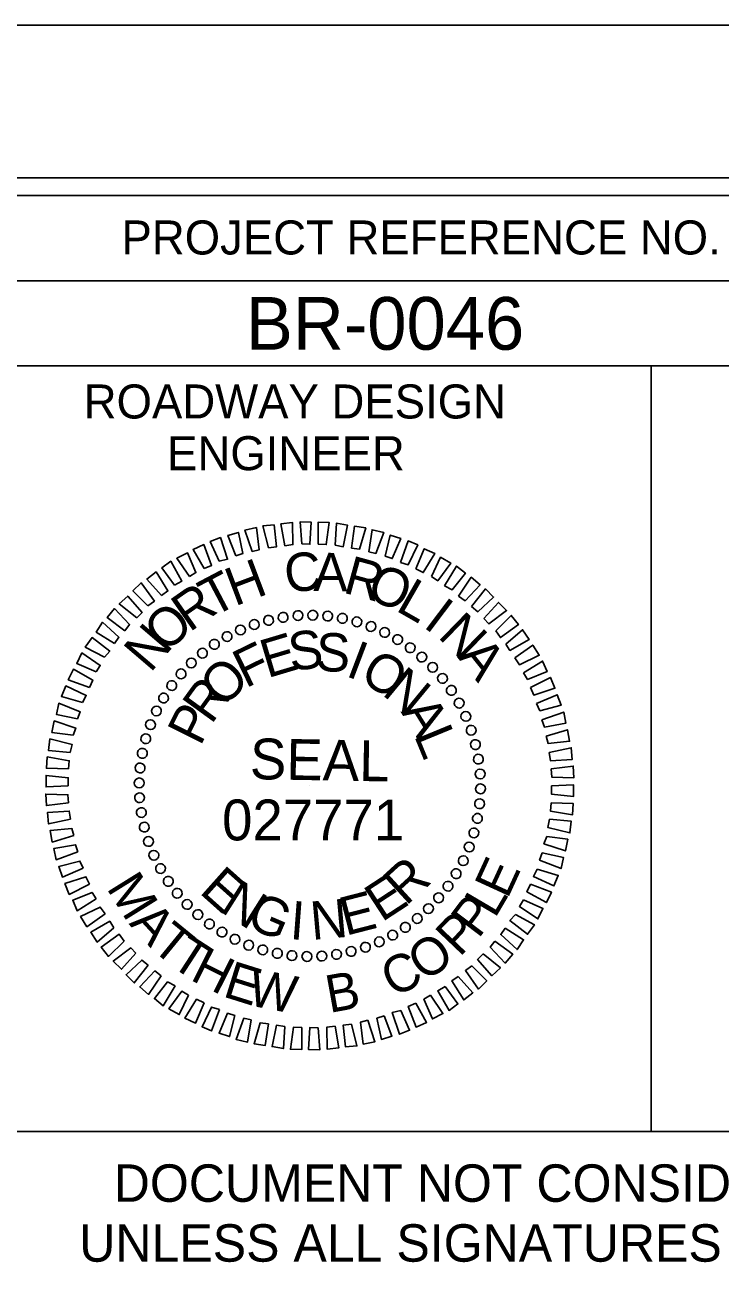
# Model space of a CAD drawing. Extents: x 1019474 to 1021158, y 503201 to 504732.
# Drawn here: x 1020949.2 to 1021051.4, y 504115.2 to 504300.7 of the extents above; entities that cross this region are included whole.
import ezdxf

# ---------------------------------------------------------------- set-up
doc = ezdxf.new("R2010")
doc.units = 0
for name, color, linetype in [('Sheet Cutting Line CELL', 7, 'Continuous'), ('Sheet Data Field CELL', 7, 'Continuous'), ('Sheet Plot Border Inside CELL', 7, 'Continuous'), ('Sheet Plot Border Outside CELL', 7, 'Continuous'), ('Sheet Professional Seal CELL', 7, 'Continuous'), ('Sheet Profile CELL', 7, 'Continuous'), ('Sheet Sticker Exception Certification CELL', 7, 'Continuous')]:
    doc.layers.add(name, color=color, linetype=linetype)

msp = doc.modelspace()

# ---------------------------------------------------------------- linework, layer by layer
at = {"layer": 'Sheet Cutting Line CELL'}
msp.add_line((1021158.22, 504300.7), (1019474.22, 504300.7), dxfattribs=at)
at = {"layer": 'Sheet Plot Border Inside CELL'}
msp.add_lwpolyline([(1019487.22, 503223.15), (1021153.72, 503223.15), (1021153.72, 504278.25), (1019487.22, 504278.25)], close=True, dxfattribs=at)
at = {"layer": 'Sheet Plot Border Outside CELL'}
msp.add_lwpolyline([(1019474.22, 503200.7), (1021158.22, 503200.7), (1021158.22, 504300.7), (1019474.22, 504300.7)], close=True, dxfattribs=at)
at = {"layer": 'Sheet Professional Seal CELL'}
for p, q in [((1020982.86, 504212.67), (1020982.86, 504212.67)), ((1020984.96, 504213.27), (1020984.96, 504213.27)), ((1020987.16, 504213.67), (1020987.16, 504213.67)), ((1020989.31, 504213.97), (1020989.31, 504213.97)), ((1020991.51, 504214.02), (1020991.51, 504214.02)), ((1020993.71, 504213.87), (1020993.71, 504213.87)), ((1020995.86, 504213.52), (1020995.86, 504213.52)), ((1020997.96, 504213.07), (1020997.96, 504213.07)), ((1020978.91, 504210.87), (1020978.91, 504210.87)), ((1020980.86, 504211.87), (1020980.86, 504211.87)), ((1021000.06, 504212.37), (1021000.06, 504212.37)), ((1021002.06, 504211.47), (1021002.06, 504211.47)), ((1020977.01, 504209.72), (1020977.01, 504209.72)), ((1021004.01, 504210.47), (1021004.01, 504210.47)), ((1021005.81, 504209.22), (1021005.81, 504209.22)), ((1020973.61, 504206.97), (1020973.61, 504206.97)), ((1020975.26, 504208.47), (1020975.26, 504208.47)), ((1021007.56, 504207.87), (1021007.56, 504207.87)), ((1020972.11, 504205.42), (1020972.11, 504205.42)), ((1021009.11, 504206.37), (1021009.11, 504206.37)), ((1020970.76, 504203.67), (1020970.76, 504203.67)), ((1021010.61, 504204.72), (1021010.61, 504204.72)), ((1020969.51, 504201.87), (1020969.51, 504201.87)), ((1021011.86, 504202.97), (1021011.86, 504202.97)), ((1020968.51, 504199.92), (1020968.51, 504199.92)), ((1021013.01, 504201.07), (1021013.01, 504201.07)), ((1020967.61, 504197.92), (1020967.61, 504197.92)), ((1021014.01, 504199.12), (1021014.01, 504199.12)), ((1020966.91, 504195.82), (1020966.91, 504195.82)), ((1021014.81, 504197.12), (1021014.81, 504197.12)), ((1021015.41, 504195.02), (1021015.41, 504195.02)), ((1020966.46, 504193.72), (1020966.46, 504193.72)), ((1021015.81, 504192.82), (1021015.81, 504192.82)), ((1020966.11, 504191.57), (1020966.11, 504191.57)), ((1021016.11, 504190.67), (1021016.11, 504190.67)), ((1020965.96, 504189.37), (1020965.96, 504189.37)), ((1020991.06, 504188.92), (1020991.06, 504188.92)), ((1021016.16, 504188.47), (1021016.16, 504188.47)), ((1020966.01, 504187.17), (1020966.01, 504187.17)), ((1020966.31, 504185.02), (1020966.31, 504185.02)), ((1021016.01, 504186.27), (1021016.01, 504186.27)), ((1020966.71, 504182.82), (1020966.71, 504182.82)), ((1021015.66, 504184.12), (1021015.66, 504184.12)), ((1021015.21, 504182.02), (1021015.21, 504182.02)), ((1020967.31, 504180.72), (1020967.31, 504180.72)), ((1021014.51, 504179.92), (1021014.51, 504179.92)), ((1020968.11, 504178.72), (1020968.11, 504178.72)), ((1021013.61, 504177.92), (1021013.61, 504177.92)), ((1020969.11, 504176.77), (1020969.11, 504176.77)), ((1021012.61, 504175.97), (1021012.61, 504175.97)), ((1020970.26, 504174.87), (1020970.26, 504174.87)), ((1021011.36, 504174.17), (1021011.36, 504174.17)), ((1020971.51, 504173.12), (1020971.51, 504173.12)), ((1021010.01, 504172.42), (1021010.01, 504172.42)), ((1020973.01, 504171.47), (1020973.01, 504171.47)), ((1020974.56, 504169.97), (1020974.56, 504169.97)), ((1021008.51, 504170.87), (1021008.51, 504170.87)), ((1020976.31, 504168.62), (1020976.31, 504168.62)), ((1021005.11, 504168.12), (1021005.11, 504168.12)), ((1021006.86, 504169.37), (1021006.86, 504169.37)), ((1020978.11, 504167.37), (1020978.11, 504167.37)), ((1020980.06, 504166.37), (1020980.06, 504166.37)), ((1021003.21, 504166.97), (1021003.21, 504166.97)), ((1020982.06, 504165.47), (1020982.06, 504165.47)), ((1020984.16, 504164.77), (1020984.16, 504164.77)), ((1020986.26, 504164.32), (1020986.26, 504164.32)), ((1020997.16, 504164.57), (1020997.16, 504164.57)), ((1020999.26, 504165.17), (1020999.26, 504165.17)), ((1021001.26, 504165.97), (1021001.26, 504165.97)), ((1020988.41, 504163.97), (1020988.41, 504163.97)), ((1020990.61, 504163.82), (1020990.61, 504163.82)), ((1020992.81, 504163.87), (1020992.81, 504163.87)), ((1020994.96, 504164.17), (1020994.96, 504164.17))]:
    msp.add_line(p, q, dxfattribs=at)
for points in [[(1020984.96, 504223.92), (1020984.16, 504227.12), (1020985.81, 504227.27), (1020986.16, 504224.07)], [(1020987.36, 504224.22), (1020986.81, 504227.42), (1020988.51, 504227.62), (1020988.56, 504224.37)], [(1020989.86, 504224.47), (1020989.61, 504227.72), (1020991.26, 504227.67), (1020991.06, 504224.42)], [(1020992.26, 504224.42), (1020992.26, 504227.67), (1020993.91, 504227.62), (1020993.46, 504224.37)], [(1020994.76, 504224.27), (1020994.96, 504227.52), (1020996.61, 504227.22), (1020995.96, 504224.07)], [(1020977.71, 504221.92), (1020976.41, 504224.82), (1020977.91, 504225.42), (1020978.96, 504222.22)], [(1020980.16, 504222.72), (1020979.01, 504225.72), (1020980.56, 504226.17), (1020981.21, 504223.07)], [(1020982.56, 504223.37), (1020981.51, 504226.52), (1020983.21, 504226.87), (1020983.61, 504223.62)], [(1020997.16, 504223.87), (1020997.61, 504227.07), (1020999.26, 504226.82), (1020998.36, 504223.72)], [(1020999.71, 504223.32), (1021000.21, 504226.57), (1021001.91, 504226.17), (1021000.76, 504223.07)], [(1021002.11, 504222.67), (1021002.86, 504225.77), (1021004.41, 504225.27), (1021003.16, 504222.32)], [(1020975.51, 504220.87), (1020973.91, 504223.67), (1020975.46, 504224.37), (1020976.61, 504221.32)], [(1021004.36, 504221.77), (1021005.51, 504224.92), (1021006.91, 504224.32), (1021005.51, 504221.42)], [(1021006.61, 504220.82), (1021007.86, 504223.77), (1021009.41, 504223.07), (1021007.71, 504220.27)], [(1020971.16, 504218.42), (1020969.31, 504220.97), (1020970.61, 504221.92), (1020972.26, 504219.02)], [(1020973.36, 504219.67), (1020971.51, 504222.37), (1020973.06, 504223.17), (1020974.31, 504220.27)], [(1021008.91, 504219.67), (1021010.26, 504222.52), (1021011.76, 504221.67), (1021009.86, 504219.07)], [(1020969.26, 504216.92), (1020967.11, 504219.32), (1020968.46, 504220.37), (1020970.21, 504217.57)], [(1021010.86, 504218.32), (1021012.61, 504221.22), (1021013.91, 504220.17), (1021011.96, 504217.72)], [(1020967.26, 504215.37), (1020965.06, 504217.57), (1020966.26, 504218.77), (1020968.21, 504216.07)], [(1021012.91, 504216.82), (1021014.76, 504219.57), (1021016.06, 504218.47), (1021013.86, 504216.12)], [(1020965.61, 504213.62), (1020963.06, 504215.67), (1020964.31, 504216.82), (1020966.41, 504214.42)], [(1021014.81, 504215.27), (1021016.86, 504217.87), (1021018.06, 504216.67), (1021015.76, 504214.52)], [(1020963.86, 504211.72), (1020961.26, 504213.67), (1020962.36, 504214.97), (1020964.56, 504212.62)], [(1021016.61, 504213.52), (1021018.76, 504215.87), (1021019.96, 504214.67), (1021017.36, 504212.72)], [(1020962.36, 504209.82), (1020959.66, 504211.52), (1020960.61, 504212.97), (1020963.01, 504210.77)], [(1021018.36, 504211.72), (1021020.66, 504213.97), (1021021.71, 504212.62), (1021019.06, 504210.72)], [(1020960.86, 504207.82), (1020958.06, 504209.32), (1020959.06, 504210.72), (1020961.66, 504208.72)], [(1021019.86, 504209.77), (1021022.31, 504211.87), (1021023.26, 504210.42), (1021020.46, 504208.82)], [(1021021.16, 504207.72), (1021023.81, 504209.62), (1021024.76, 504208.12), (1021021.86, 504206.72)], [(1020959.66, 504205.67), (1020956.81, 504206.92), (1020957.56, 504208.47), (1020960.26, 504206.62)], [(1021022.46, 504205.52), (1021025.26, 504207.27), (1021025.91, 504205.72), (1021023.06, 504204.57)], [(1020958.66, 504203.37), (1020955.56, 504204.52), (1020956.31, 504206.07), (1020959.16, 504204.47)], [(1020957.66, 504201.17), (1020954.56, 504202.07), (1020955.21, 504203.62), (1020958.21, 504202.22)], [(1021023.46, 504203.37), (1021026.41, 504204.87), (1021027.06, 504203.27), (1021023.96, 504202.27)], [(1021024.36, 504201.02), (1021027.41, 504202.32), (1021027.96, 504200.77), (1021024.86, 504199.97)], [(1020956.91, 504198.77), (1020953.81, 504199.42), (1020954.16, 504201.07), (1020957.31, 504199.82)], [(1021025.16, 504198.62), (1021028.36, 504199.77), (1021028.66, 504198.12), (1021025.51, 504197.57)], [(1020956.26, 504196.37), (1020953.16, 504196.77), (1020953.51, 504198.47), (1020956.66, 504197.42)], [(1020955.86, 504193.82), (1020952.66, 504194.12), (1020952.86, 504195.82), (1020956.11, 504195.02)], [(1021025.76, 504196.22), (1021028.91, 504197.17), (1021029.21, 504195.47), (1021026.06, 504195.17)], [(1021026.21, 504193.82), (1021029.46, 504194.52), (1021029.61, 504192.82), (1021026.41, 504192.62)], [(1020955.61, 504191.42), (1020952.36, 504191.52), (1020952.46, 504193.17), (1020955.71, 504192.62)], [(1020955.56, 504188.92), (1020952.31, 504188.77), (1020952.31, 504190.47), (1020955.56, 504190.12)], [(1021026.51, 504191.42), (1021029.76, 504191.82), (1021029.86, 504190.12), (1021026.61, 504190.22)], [(1021026.56, 504188.92), (1021029.81, 504189.07), (1021029.81, 504187.37), (1021026.56, 504187.72)], [(1020955.61, 504186.42), (1020952.36, 504186.02), (1020952.26, 504187.72), (1020955.51, 504187.62)], [(1020955.91, 504184.02), (1020952.66, 504183.32), (1020952.51, 504185.02), (1020955.71, 504185.22)], [(1021026.51, 504186.42), (1021029.76, 504186.32), (1021029.66, 504184.67), (1021026.41, 504185.22)], [(1021026.26, 504184.02), (1021029.46, 504183.72), (1021029.26, 504182.02), (1021026.01, 504182.82)], [(1020956.36, 504181.62), (1020953.21, 504180.67), (1020952.91, 504182.37), (1020956.06, 504182.67)], [(1021025.86, 504181.47), (1021028.96, 504181.07), (1021028.61, 504179.37), (1021025.46, 504180.42)], [(1020956.96, 504179.22), (1020953.76, 504178.07), (1020953.46, 504179.72), (1020956.61, 504180.27)], [(1021025.21, 504179.07), (1021028.31, 504178.42), (1021027.96, 504176.77), (1021024.81, 504178.02)], [(1020957.76, 504176.82), (1020954.71, 504175.52), (1020954.16, 504177.07), (1020957.26, 504177.87)], [(1020958.66, 504174.47), (1020955.71, 504172.97), (1020955.06, 504174.57), (1020958.16, 504175.57)], [(1021024.46, 504176.67), (1021027.56, 504175.77), (1021026.91, 504174.22), (1021023.91, 504175.62)], [(1021023.46, 504174.47), (1021026.56, 504173.32), (1021025.81, 504171.77), (1021022.96, 504173.37)], [(1020959.66, 504172.32), (1020956.86, 504170.57), (1020956.21, 504172.12), (1020959.06, 504173.27)], [(1021022.46, 504172.17), (1021025.31, 504170.92), (1021024.56, 504169.37), (1021021.86, 504171.22)], [(1020960.96, 504170.12), (1020958.31, 504168.22), (1020957.36, 504169.72), (1020960.26, 504171.12)], [(1021021.26, 504170.02), (1021024.06, 504168.52), (1021023.06, 504167.12), (1021020.46, 504169.12)], [(1020962.26, 504168.07), (1020959.81, 504165.97), (1020958.86, 504167.42), (1020961.66, 504169.02)], [(1021019.76, 504168.02), (1021022.46, 504166.32), (1021021.51, 504164.87), (1021019.11, 504167.07)], [(1020963.76, 504166.12), (1020961.46, 504163.87), (1020960.41, 504165.22), (1020963.06, 504167.12)], [(1021018.26, 504166.12), (1021020.86, 504164.17), (1021019.76, 504162.87), (1021017.56, 504165.22)], [(1020965.51, 504164.32), (1020963.36, 504161.97), (1020962.16, 504163.17), (1020964.76, 504165.12)], [(1021016.51, 504164.22), (1021019.06, 504162.17), (1021017.81, 504161.02), (1021015.71, 504163.42)], [(1020967.31, 504162.57), (1020965.26, 504159.97), (1020964.06, 504161.17), (1020966.36, 504163.32)], [(1021014.86, 504162.47), (1021017.06, 504160.27), (1021015.86, 504159.07), (1021013.91, 504161.77)], [(1020969.21, 504161.02), (1020967.36, 504158.27), (1020966.06, 504159.37), (1020968.26, 504161.72)], [(1021012.86, 504160.92), (1021015.01, 504158.52), (1021013.66, 504157.47), (1021011.91, 504160.27)], [(1020971.26, 504159.52), (1020969.51, 504156.62), (1020968.21, 504157.67), (1020970.16, 504160.12)], [(1020973.21, 504158.17), (1020971.86, 504155.32), (1020970.36, 504156.17), (1020972.26, 504158.77)], [(1021010.96, 504159.42), (1021012.81, 504156.87), (1021011.51, 504155.92), (1021009.86, 504158.82)], [(1020975.51, 504157.02), (1020974.26, 504154.07), (1020972.71, 504154.77), (1020974.41, 504157.57)], [(1021006.61, 504156.97), (1021008.21, 504154.17), (1021006.66, 504153.47), (1021005.51, 504156.52)], [(1021008.76, 504158.17), (1021010.61, 504155.47), (1021009.06, 504154.67), (1021007.81, 504157.57)], [(1020977.76, 504156.07), (1020976.61, 504152.92), (1020975.21, 504153.52), (1020976.61, 504156.42)], [(1020980.01, 504155.17), (1020979.26, 504152.07), (1020977.71, 504152.57), (1020978.96, 504155.52)], [(1021001.96, 504155.12), (1021003.11, 504152.12), (1021001.56, 504151.67), (1021000.91, 504154.77)], [(1021004.41, 504155.92), (1021005.71, 504153.02), (1021004.21, 504152.42), (1021003.16, 504155.62)], [(1020982.41, 504154.52), (1020981.91, 504151.27), (1020980.21, 504151.67), (1020981.36, 504154.77)], [(1020984.96, 504153.97), (1020984.51, 504150.77), (1020982.86, 504151.02), (1020983.76, 504154.12)], [(1020987.36, 504153.57), (1020987.16, 504150.32), (1020985.51, 504150.62), (1020986.16, 504153.77)], [(1020989.86, 504153.42), (1020989.86, 504150.17), (1020988.21, 504150.22), (1020988.66, 504153.47)], [(1020992.26, 504153.37), (1020992.51, 504150.12), (1020990.86, 504150.17), (1020991.06, 504153.42)], [(1020994.76, 504153.62), (1020995.31, 504150.42), (1020993.61, 504150.22), (1020993.56, 504153.47)], [(1020997.16, 504153.92), (1020997.96, 504150.72), (1020996.31, 504150.57), (1020995.96, 504153.77)], [(1020999.56, 504154.47), (1021000.61, 504151.32), (1020998.91, 504150.97), (1020998.51, 504154.22)]]:
    msp.add_lwpolyline(points, close=True, dxfattribs=at)
for centre, major_axis in [((1020987.13, 504213.7), (-0.113, 0.711)), ((1020989.31, 504213.94), (-0.05, 0.718)), ((1020991.49, 504214), (0.013, 0.72)), ((1020993.68, 504213.87), (0.075, 0.716)), ((1020995.84, 504213.54), (0.137, 0.707)), ((1020980.86, 504211.84), (-0.293, 0.658)), ((1020982.89, 504212.64), (-0.234, 0.681)), ((1020984.99, 504213.26), (-0.174, 0.699)), ((1020997.97, 504213.03), (0.198, 0.692)), ((1021000.04, 504212.34), (0.258, 0.672)), ((1020978.9, 504210.86), (-0.349, 0.63)), ((1021002.05, 504211.47), (0.316, 0.647)), ((1021003.97, 504210.42), (0.371, 0.617)), ((1020975.27, 504208.42), (-0.453, 0.56)), ((1020977.03, 504209.72), (-0.403, 0.597)), ((1021005.8, 504209.21), (0.423, 0.582)), ((1020973.63, 504206.97), (-0.5, 0.518)), ((1021007.51, 504207.85), (0.472, 0.543)), ((1021009.1, 504206.35), (0.518, 0.5)), ((1020972.13, 504205.38), (-0.543, 0.472)), ((1021010.55, 504204.71), (0.56, 0.453)), ((1020970.77, 504203.67), (-0.582, 0.423)), ((1021011.85, 504202.95), (0.597, 0.403)), ((1020969.56, 504201.84), (-0.617, 0.371)), ((1021012.99, 504201.08), (0.63, 0.349)), ((1020968.51, 504199.92), (-0.647, 0.316)), ((1021013.97, 504199.13), (0.658, 0.293)), ((1020967.64, 504197.91), (-0.672, 0.258)), ((1021014.77, 504197.09), (0.681, 0.234)), ((1020966.95, 504195.84), (-0.692, 0.198)), ((1021015.39, 504194.99), (0.699, 0.174)), ((1020966.44, 504193.71), (-0.707, 0.137)), ((1020966.11, 504191.55), (-0.716, 0.075)), ((1021015.83, 504192.85), (0.711, 0.113)), ((1021016.08, 504190.67), (0.718, 0.05)), ((1020965.98, 504189.36), (-0.72, 0.013)), ((1021016.13, 504188.49), (0.72, -0.013)), ((1020966.04, 504187.18), (-0.718, -0.05)), ((1021016, 504186.3), (0.716, -0.075)), ((1020966.29, 504185), (-0.711, -0.113)), ((1021015.68, 504184.14), (0.707, -0.137)), ((1020966.72, 504182.86), (-0.699, -0.174)), ((1021015.16, 504182.01), (0.692, -0.198)), ((1020967.34, 504180.76), (-0.681, -0.234)), ((1020968.14, 504178.72), (-0.658, -0.293)), ((1021014.47, 504179.94), (0.672, -0.258)), ((1020969.12, 504176.77), (-0.63, -0.349)), ((1021013.6, 504177.93), (0.647, -0.316)), ((1020970.26, 504174.9), (-0.597, -0.403)), ((1021012.55, 504176.01), (0.617, -0.371)), ((1020971.57, 504173.14), (-0.56, -0.453)), ((1021011.35, 504174.18), (0.582, -0.423)), ((1020973.02, 504171.5), (-0.518, -0.5)), ((1021008.48, 504170.88), (0.5, -0.518)), ((1021009.98, 504172.47), (0.543, -0.472)), ((1020974.6, 504170), (-0.472, -0.543)), ((1021006.84, 504169.43), (0.453, -0.56)), ((1020976.31, 504168.63), (-0.423, -0.582)), ((1020978.14, 504167.43), (-0.371, -0.617)), ((1021005.08, 504168.13), (0.403, -0.597)), ((1020980.06, 504166.38), (-0.316, -0.647)), ((1020982.07, 504165.51), (-0.258, -0.672)), ((1021001.26, 504166.01), (0.293, -0.658)), ((1021003.22, 504166.99), (0.349, -0.63)), ((1020984.14, 504164.82), (-0.198, -0.692)), ((1020986.27, 504164.31), (-0.137, -0.707)), ((1020988.43, 504163.98), (-0.075, -0.716)), ((1020990.62, 504163.85), (-0.013, -0.72)), ((1020992.81, 504163.91), (0.05, -0.718)), ((1020994.98, 504164.15), (0.113, -0.711)), ((1020997.12, 504164.59), (0.174, -0.699)), ((1020999.22, 504165.21), (0.234, -0.681))]:
    msp.add_ellipse(centre, major_axis=major_axis, ratio=0.999708, dxfattribs=at)
at = {"layer": 'Sheet Profile CELL'}
for p, q in [((1020941.17, 504263.15), (1021141.22, 504263.15)), ((1021041.22, 504250.65), (1021041.22, 504138.2))]:
    msp.add_line(p, q, dxfattribs=at)
for points in [[(1021141.22, 504275.7), (1019641.22, 504275.7), (1019641.22, 503225.7), (1021141.22, 503225.7)], [(1020941.17, 504275.7), (1021141.22, 504275.7), (1021141.22, 504250.65), (1020941.17, 504250.65)], [(1020941.17, 504250.65), (1021041.22, 504250.65), (1021041.22, 504138.15), (1020941.17, 504138.15)], [(1021041.22, 504250.65), (1021141.22, 504250.65), (1021141.22, 504138.15), (1021041.22, 504138.15)]]:
    msp.add_lwpolyline(points, close=True, dxfattribs=at)
at = {"layer": 'Sheet Sticker Exception Certification CELL'}
msp.add_line((1020941.17, 504138.15), (1021141.21, 504138.15), dxfattribs=at)
msp.add_line((1020941.17, 504138.15), (1021141.21, 504138.15), dxfattribs=at)

# ---------------------------------------------------------------- texts
at = {"layer": 'Sheet Data Field CELL'}
msp.add_text('BR-0046', height=7.75, dxfattribs=at).set_placement((1020981.65, 504253.01))
at = {"layer": 'Sheet Professional Seal CELL'}
for s, height, rotation, p in [('H', 5.64, 20.6195, (1020980.01, 504215.27)), ('C', 5.64, 6.2199, (1020987.61, 504217.27)), ('A', 5.64, 359.0203, (1020991.56, 504217.57)), ('R', 5.64, 344.6211, (1020995.76, 504217.37)), ('T', 5.64, 27.8198, (1020976.76, 504213.62)), ('O', 5.64, 337.4212, (1020999.11, 504216.62)), ('R', 5.64, 35.0205, (1020973.36, 504211.42)), ('L', 5.64, 330.2209, (1021003.51, 504214.77)), ('I', 5.64, 323.0201, (1021007.56, 504212.37)), ('O', 5.64, 42.2217, (1020969.91, 504208.32)), ('N', 5.64, 315.8189, (1021009.71, 504210.82)), ('N', 5.64, 49.4235, (1020967.61, 504205.42)), ('E', 5.64, 16.6111, (1020984.81, 504204.72)), ('S', 5.64, 7.2556, (1020988.26, 504205.77)), ('S', 5.64, 357.9004, (1020991.86, 504205.82)), ('F', 5.64, 25.967, (1020981.61, 504203.22)), ('I', 5.64, 339.1896, (1020996.16, 504205.12)), ('A', 5.64, 308.6172, (1021012.66, 504207.87)), ('O', 5.64, 44.6812, (1020978.31, 504200.27)), ('O', 5.64, 329.8335, (1020998.16, 504204.42)), ('N', 5.64, 320.4766, (1021001.51, 504202.42)), ('R', 5.64, 54.0397, (1020976.56, 504197.82)), ('P', 5.64, 63.3989, (1020974.96, 504194.62)), ('A', 5.64, 301.7603, (1021004.36, 504199.82)), ('L', 5.64, 292.4008, (1021006.31, 504196.37)), ('SEAL', 5.998, 359, (1020982.21, 504189.92)), ('027771', 5.998, 360, (1020978.16, 504180.92)), ('R', 5.64, 42.4814, (1021005.16, 504171.17)), ('E', 5.5, 65.3458, (1021020.08, 504172.18)), ('M', 5.5, 301.8863, (1020961.09, 504173.94)), ('E', 5.64, 318.2769, (1020974.66, 504173.27)), ('E', 5.64, 33.1241, (1021001.61, 504168.82)), ('N', 5.64, 327.634, (1020977.66, 504170.57)), ('E', 5.64, 14.4118, (1020996.31, 504166.87)), ('G', 5.64, 336.9902, (1020981.46, 504168.32)), ('I', 5.64, 355.7012, (1020988.01, 504166.42)), ('N', 5.64, 5.0564, (1020991.36, 504166.27)), ('P', 5.5, 52.9527, (1021015.81, 504166.34)), ('L', 5.5, 59.5356, (1021018.24, 504169.33)), ('A', 5.5, 312.5622, (1020964.38, 504168.65)), ('P', 5.5, 46.3697, (1021013.06, 504163.65)), ('T', 5.5, 320.748, (1020967.54, 504165.06)), ('T', 5.5, 327.0447, (1020970.3, 504162.62)), ('O', 5.5, 35.6652, (1021007.98, 504160.01)), ('H', 5.5, 333.3415, (1020973.31, 504160.5)), ('C', 5.5, 26.7925, (1021003.32, 504157.74)), ('E', 5.5, 342.5863, (1020978.11, 504158.02)), ('W', 5.5, 349.1693, (1020981.73, 504156.74)), ('B', 5.5, 10.2205, (1020993.92, 504155.54))]:
    msp.add_text(s, height=height, rotation=rotation, dxfattribs=at).set_placement(p)
at = {"layer": 'Sheet Profile CELL'}
for s, height, p in [('PROJECT REFERENCE NO.', 5.0001, (1020963.38, 504267.01)), ('ROADWAY DESIGN', 5.0001, (1020957.83, 504242.91)), ('ENGINEER', 5, (1020970.08, 504235.31))]:
    msp.add_text(s, height=height, dxfattribs=at).set_placement(p)
at = {"layer": 'Sheet Sticker Exception Certification CELL'}
for s, p in [('DOCUMENT NOT CONSIDERED FINAL', (1020962.24, 504127.8)), ('DOCUMENT NOT CONSIDERED FINAL', (1020962.24, 504127.8)), ('UNLESS ALL SIGNATURES COMPLETED', (1020957.17, 504119)), ('UNLESS ALL SIGNATURES COMPLETED', (1020957.17, 504119))]:
    msp.add_text(s, height=5.5, dxfattribs=at).set_placement(p)

doc.saveas('drawing.dxf')
